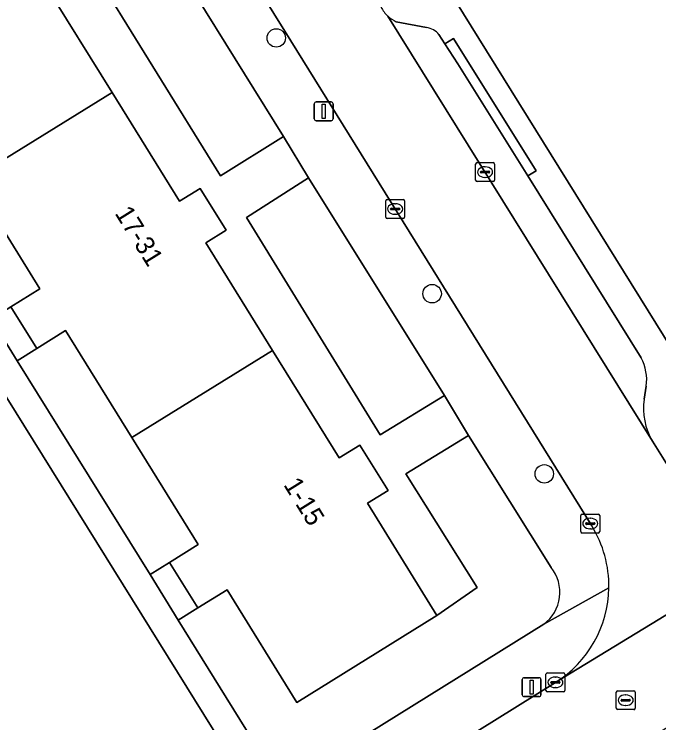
# Model space of a CAD drawing. Extents: x 160030 to 160839, y 385325 to 386450.
# Drawn here: x 160299.48 to 160333.64, y 386175.84 to 386213.39 of the extents above; entities that cross this region are included whole.
import ezdxf

# ---------------------------------------------------------------- set-up
doc = ezdxf.new("R2010")
doc.units = 0
for name, color, linetype in [('IMGEO_Boom', 7, 'Continuous'), ('IMGEO_Erf', 7, 'Continuous'), ('IMGEO_Groenvoorziening', 7, 'Continuous'), ('IMGEO_Haag', 7, 'Continuous'), ('IMGEO_Kolk', 7, 'Continuous'), ('IMGEO_Lichtmast', 7, 'Continuous'), ('IMGEO_Pand', 7, 'Continuous'), ('IMGEO_Pand_nummerreeks', 7, 'Continuous'), ('IMGEO_Parkeervlak_open', 7, 'Continuous'), ('IMGEO_Rijbaan_lokaal_open', 7, 'Continuous'), ('IMGEO_Rioolput', 7, 'Continuous'), ('IMGEO_Voetpad_op_trap', 7, 'Continuous'), ('IMGEO_Voetpad_open', 7, 'Continuous')]:
    doc.layers.add(name, color=color, linetype=linetype)

msp = doc.modelspace()

# ---------------------------------------------------------------- linework, layer by layer
at = {"layer": 'IMGEO_Boom'}
for centre in [(160313.371, 386212.128), (160321.633, 386198.577), (160327.575, 386189.032)]:
    msp.add_circle(centre, 0.489, dxfattribs=at)
at = {"layer": 'IMGEO_Erf'}
msp.add_lwpolyline([(160304.123, 386244.251), (160337.312, 386190.843)], dxfattribs=at)
at = {"layer": 'IMGEO_Groenvoorziening'}
for points in [[(160301.386, 386164.795), (160312.412, 386171.653), (160275.723, 386230.616), (160264.734, 386223.762)], [(160327.936, 386184.073), (160323.561, 386191.066), (160320.231, 386189.03), (160324.014, 386183.004), (160321.888, 386181.533), (160314.462, 386176.925), (160310.764, 386182.883), (160309.22, 386181.925), (160308.182, 386181.28), (160313.676, 386172.439), (160327.55, 386181.067)]]:
    msp.add_lwpolyline(points, dxfattribs=at)
for points in [[(160306.568, 386218.474), (160303.238, 386216.424), (160310.423, 386204.827), (160313.752, 386206.898)], [(160293.617, 386210.48), (160292.05, 386209.507), (160291.031, 386208.874), (160298.269, 386197.229), (160299.312, 386197.878), (160300.847, 386198.83), (160297.243, 386204.638)], [(160315.078, 386204.713), (160311.788, 386202.622), (160318.885, 386191.095), (160322.284, 386193.185)], [(160305.72, 386190.952), (160302.202, 386196.621), (160300.679, 386195.676), (160299.637, 386195.028), (160306.682, 386183.693), (160307.722, 386184.339), (160309.24, 386185.281)]]:
    msp.add_lwpolyline(points, close=True, dxfattribs=at)
msp.add_arc((160326.298, 386182.756), 2.102, 306.5541, 38.8113, dxfattribs=at)
at = {"layer": 'IMGEO_Haag'}
for points in [[(160306.568, 386218.474), (160303.238, 386216.424), (160310.423, 386204.827), (160313.752, 386206.898)], [(160315.078, 386204.713), (160311.788, 386202.622), (160318.885, 386191.095), (160322.284, 386193.185)]]:
    msp.add_lwpolyline(points, close=True, dxfattribs=at)
at = {"layer": 'IMGEO_Kolk'}
for p, q in [((160323.937, 386204.594), (160323.937, 386205.446)), ((160324.012, 386205.52), (160324.864, 386205.52)), ((160324.425, 386205.3), (160324.45, 386205.3)), ((160324.938, 386205.446), (160324.938, 386204.594)), ((160324.196, 386205.014), (160324.196, 386205.026)), ((160324.634, 386204.977), (160324.236, 386204.977)), ((160324.239, 386205.063), (160324.637, 386205.063)), ((160324.68, 386205.026), (160324.68, 386205.014)), ((160324.864, 386204.52), (160324.012, 386204.52)), ((160324.448, 386204.74), (160324.423, 386204.74)), ((160319.17, 386202.64), (160319.17, 386203.492)), ((160319.245, 386203.566), (160320.097, 386203.566)), ((160319.658, 386203.346), (160319.683, 386203.346)), ((160320.171, 386203.492), (160320.171, 386202.64)), ((160319.429, 386203.06), (160319.429, 386203.072)), ((160319.867, 386203.023), (160319.469, 386203.023)), ((160319.472, 386203.109), (160319.87, 386203.109)), ((160319.913, 386203.072), (160319.913, 386203.06)), ((160320.097, 386202.566), (160319.245, 386202.566)), ((160319.681, 386202.786), (160319.656, 386202.786)), ((160329.511, 386185.971), (160329.511, 386186.823)), ((160329.586, 386186.897), (160330.438, 386186.897)), ((160330.512, 386186.823), (160330.512, 386185.971)), ((160329.813, 386186.44), (160330.211, 386186.44)), ((160329.999, 386186.677), (160330.024, 386186.677)), ((160329.77, 386186.391), (160329.77, 386186.403)), ((160330.208, 386186.354), (160329.81, 386186.354)), ((160330.022, 386186.117), (160329.997, 386186.117)), ((160330.254, 386186.403), (160330.254, 386186.391)), ((160330.438, 386185.897), (160329.586, 386185.897)), ((160327.663, 386177.557), (160327.663, 386178.409)), ((160327.738, 386178.483), (160328.59, 386178.483)), ((160328.151, 386178.263), (160328.176, 386178.263)), ((160328.664, 386178.409), (160328.664, 386177.557)), ((160327.922, 386177.977), (160327.922, 386177.989)), ((160328.36, 386177.94), (160327.962, 386177.94)), ((160327.965, 386178.026), (160328.363, 386178.026)), ((160328.406, 386177.989), (160328.406, 386177.977)), ((160328.59, 386177.483), (160327.738, 386177.483)), ((160328.174, 386177.703), (160328.149, 386177.703))]:
    msp.add_line(p, q, dxfattribs=at)
for points in [[(160323.937, 386204.594), (160323.937, 386205.446)], [(160324.012, 386205.52), (160324.864, 386205.52)], [(160324.938, 386205.446), (160324.938, 386204.594)], [(160324.864, 386204.52), (160324.012, 386204.52)], [(160319.17, 386202.64), (160319.17, 386203.492)], [(160319.245, 386203.566), (160320.097, 386203.566)], [(160320.171, 386203.492), (160320.171, 386202.64)], [(160320.097, 386202.566), (160319.245, 386202.566)], [(160329.511, 386185.971), (160329.511, 386186.823)], [(160329.586, 386186.897), (160330.438, 386186.897)], [(160330.512, 386186.823), (160330.512, 386185.971)], [(160330.438, 386185.897), (160329.586, 386185.897)], [(160327.663, 386177.557), (160327.663, 386178.409)], [(160327.738, 386178.483), (160328.59, 386178.483)], [(160328.664, 386178.409), (160328.664, 386177.557)], [(160328.59, 386177.483), (160327.738, 386177.483)]]:
    msp.add_lwpolyline(points, dxfattribs=at)
for centre, radius, start, end in [((160324.014, 386205.444), 0.0765, 91.552, 178.448), ((160324.014, 386205.444), 0.0765, 91.552, 178.448), ((160324.862, 386205.444), 0.0765, 1.552, 88.448), ((160324.862, 386205.444), 0.0765, 1.552, 88.448), ((160324.236, 386205.023), 0.0403, 85.8775, 175.7526), ((160324.233, 386205.013), 0.0366, 178.938, 274.7102), ((160324.637, 386205.02), 0.043, 264.8664, 352.4533), ((160324.641, 386205.025), 0.0386, 1.7309, 96.639), ((160324.014, 386204.596), 0.0765, 181.552, 268.448), ((160324.014, 386204.596), 0.0765, 181.552, 268.448), ((160324.862, 386204.596), 0.0765, 271.552, 358.448), ((160324.862, 386204.596), 0.0765, 271.552, 358.448), ((160319.247, 386203.49), 0.0765, 91.552, 178.448), ((160319.247, 386203.49), 0.0765, 91.552, 178.448), ((160320.095, 386203.49), 0.0765, 1.552, 88.448), ((160320.095, 386203.49), 0.0765, 1.552, 88.448), ((160319.469, 386203.069), 0.0403, 85.8775, 175.7526), ((160319.466, 386203.059), 0.0366, 178.938, 274.7102), ((160319.87, 386203.066), 0.043, 264.8664, 352.4533), ((160319.874, 386203.071), 0.0386, 1.7309, 96.639), ((160319.247, 386202.642), 0.0765, 181.552, 268.448), ((160319.247, 386202.642), 0.0765, 181.552, 268.448), ((160320.095, 386202.642), 0.0765, 271.552, 358.448), ((160320.095, 386202.642), 0.0765, 271.552, 358.448), ((160329.588, 386186.821), 0.0765, 91.552, 178.448), ((160329.588, 386186.821), 0.0765, 91.552, 178.448), ((160330.436, 386186.821), 0.0765, 1.552, 88.448), ((160330.436, 386186.821), 0.0765, 1.552, 88.448), ((160329.81, 386186.4), 0.0403, 85.8775, 175.7526), ((160330.215, 386186.402), 0.0386, 1.7309, 96.639), ((160329.807, 386186.39), 0.0366, 178.938, 274.7102), ((160330.211, 386186.397), 0.043, 264.8664, 352.4533), ((160329.588, 386185.973), 0.0765, 181.552, 268.448), ((160329.588, 386185.973), 0.0765, 181.552, 268.448), ((160330.436, 386185.973), 0.0765, 271.552, 358.448), ((160330.436, 386185.973), 0.0765, 271.552, 358.448), ((160327.74, 386178.407), 0.0765, 91.552, 178.448), ((160327.74, 386178.407), 0.0765, 91.552, 178.448), ((160328.588, 386178.407), 0.0765, 1.552, 88.448), ((160328.588, 386178.407), 0.0765, 1.552, 88.448), ((160327.962, 386177.986), 0.0403, 85.8775, 175.7526), ((160327.959, 386177.976), 0.0366, 178.938, 274.7102), ((160328.363, 386177.983), 0.043, 264.8664, 352.4533), ((160328.367, 386177.988), 0.0386, 1.7309, 96.639), ((160327.74, 386177.559), 0.0765, 181.552, 268.448), ((160327.74, 386177.559), 0.0765, 181.552, 268.448), ((160328.588, 386177.559), 0.0765, 271.552, 358.448), ((160328.588, 386177.559), 0.0765, 271.552, 358.448)]:
    msp.add_arc(centre, radius, start, end, dxfattribs=at)
for centre, major_axis, ratio, start_param, end_param in [((160324.424, 386205.02), (-0.387, 0.002), 0.722429, 4.712389, 7.853982), ((160324.449, 386205.02), (-0.39, 0.002), 0.717154, 1.570796, 4.712389), ((160319.657, 386203.066), (-0.387, 0.002), 0.722429, 4.712389, 7.853982), ((160319.682, 386203.066), (-0.39, 0.002), 0.717154, 1.570796, 4.712389), ((160329.998, 386186.397), (-0.387, 0.002), 0.722429, 4.712389, 7.853982), ((160330.023, 386186.397), (-0.39, 0.002), 0.717154, 1.570796, 4.712389), ((160328.15, 386177.983), (-0.387, 0.002), 0.722429, 4.712389, 7.853982), ((160328.175, 386177.983), (-0.39, 0.002), 0.717154, 1.570796, 4.712389)]:
    msp.add_ellipse(centre, major_axis=major_axis, ratio=ratio, start_param=start_param, end_param=end_param, dxfattribs=at)
at = {"layer": 'IMGEO_Lichtmast'}
for p, q in [((160315.389, 386207.842), (160315.389, 386208.642)), ((160315.389, 386208.642), (160315.389, 386207.842)), ((160315.489, 386208.742), (160316.279, 386208.742)), ((160316.279, 386208.742), (160315.489, 386208.742)), ((160316.379, 386208.642), (160316.379, 386207.842)), ((160316.379, 386207.842), (160316.379, 386208.642)), ((160316.279, 386207.742), (160315.489, 386207.742)), ((160315.489, 386207.742), (160316.279, 386207.742)), ((160326.509, 386178.227), (160327.299, 386178.227)), ((160327.299, 386178.227), (160326.509, 386178.227)), ((160326.409, 386177.327), (160326.409, 386178.127)), ((160326.409, 386178.127), (160326.409, 386177.327)), ((160327.399, 386178.127), (160327.399, 386177.327)), ((160327.399, 386177.327), (160327.399, 386178.127)), ((160327.299, 386177.227), (160326.509, 386177.227)), ((160326.509, 386177.227), (160327.299, 386177.227))]:
    msp.add_line(p, q, dxfattribs=at)
for points in [[(160315.809, 386208.617), (160315.959, 386208.617), (160315.959, 386207.867), (160315.809, 386207.867), (160315.809, 386208.617)], [(160326.829, 386178.102), (160326.979, 386178.102), (160326.979, 386177.352), (160326.829, 386177.352), (160326.829, 386178.102)]]:
    msp.add_lwpolyline(points, dxfattribs=at)
for centre, start, end in [((160315.489, 386208.642), 90, 180), ((160315.489, 386208.642), 90, 180), ((160316.279, 386208.642), 0, 90), ((160316.279, 386208.642), 360, 90), ((160315.489, 386207.842), 180, 270), ((160315.489, 386207.842), 180, 270), ((160316.279, 386207.842), 270, 0), ((160316.279, 386207.842), 270, 0), ((160326.509, 386178.127), 90, 180), ((160326.509, 386178.127), 90, 180), ((160327.299, 386178.127), 0, 90), ((160327.299, 386178.127), 360, 90), ((160326.509, 386177.327), 180, 270), ((160326.509, 386177.327), 180, 270), ((160327.299, 386177.327), 270, 0), ((160327.299, 386177.327), 270, 0)]:
    msp.add_arc(centre, 0.1, start, end, dxfattribs=at)
at = {"layer": 'IMGEO_Pand'}
for points in [[(160292.134, 386212.815), (160290.591, 386211.858), (160292.05, 386209.507), (160293.617, 386210.48), (160297.243, 386204.638), (160304.668, 386209.246), (160301.085, 386215.019), (160302.179, 386215.698), (160300.735, 386218.025), (160299.642, 386217.346), (160296.083, 386223.081), (160288.633, 386218.457)], [(160309.632, 386201.274), (160310.716, 386201.947), (160309.347, 386204.154), (160308.251, 386203.473), (160304.668, 386209.246), (160297.243, 386204.638), (160300.847, 386198.83), (160299.312, 386197.878), (160300.679, 386195.676), (160302.202, 386196.621), (160305.72, 386190.952), (160313.169, 386195.575)], [(160318.202, 386187.472), (160319.298, 386188.152), (160317.805, 386190.558), (160316.705, 386189.876), (160313.169, 386195.575), (160305.72, 386190.952), (160309.24, 386185.281), (160307.722, 386184.339), (160309.22, 386181.925), (160310.764, 386182.883), (160314.462, 386176.925), (160321.888, 386181.533)]]:
    msp.add_lwpolyline(points, close=True, dxfattribs=at)
at = {"layer": 'IMGEO_Parkeervlak_open'}
for points in [[(160319.29, 386213.287), (160333.315, 386190.762)], [(160321.331, 386212.684), (160319.733, 386212.99)], [(160322.309, 386211.819), (160321.995, 386212.306)], [(160322.991, 386210.759), (160322.309, 386211.819)], [(160326.706, 386204.817), (160322.991, 386210.759)], [(160332.704, 386195.176), (160326.706, 386204.817)], [(160332.867, 386192.983), (160332.978, 386193.672)]]:
    msp.add_lwpolyline(points, dxfattribs=at)
for centre, radius, start, end in [((160320.519, 386214.641), 1.828, 227.7743, 244.5476), ((160321.157, 386211.605), 1.093, 39.8825, 80.8138), ((160330.565, 386194.009), 2.437, 352.0445, 28.6054), ((160336.139, 386192.487), 3.309, 171.3859, 211.4224)]:
    msp.add_arc(centre, radius, start, end, dxfattribs=at)
at = {"layer": 'IMGEO_Rijbaan_lokaal_open'}
for points in [[(160296.637, 386240.069), (160313.825, 386212.492), (160330.091, 386186.273)], [(160334.54, 386188.784), (160333.315, 386190.762), (160319.29, 386213.287)], [(160296.772, 386152.353), (160320.685, 386167.257), (160326.329, 386170.774), (160326.552, 386170.947), (160340.383, 386179.474), (160340.53, 386179.543), (160347.326, 386183.769), (160344.612, 386188.134), (160343.862, 386187.679), (160342.893, 386187.018), (160342.516, 386186.712), (160328.191, 386177.996), (160328.161, 386177.98), (160316.882, 386170.942), (160304.012, 386162.957), (160303.952, 386162.913), (160289.843, 386154.224)], [(160328.161, 386177.98), (160328.191, 386177.996), (160342.516, 386186.712), (160342.893, 386187.018)]]:
    msp.add_lwpolyline(points, dxfattribs=at)
for centre, radius, start, end in [((160320.534, 386214.645), 1.841, 208.7918, 227.5119), ((160324.978, 386183.096), 6.019, 358.9949, 31.8606), ((160324.97, 386183.094), 6.028, 301.9631, 359.0113)]:
    msp.add_arc(centre, radius, start, end, dxfattribs=at)
at = {"layer": 'IMGEO_Rioolput'}
for p, q in [((160331.388, 386176.611), (160331.388, 386177.463)), ((160331.463, 386177.537), (160332.315, 386177.537)), ((160332.389, 386177.463), (160332.389, 386176.611)), ((160331.647, 386177.031), (160331.647, 386177.043)), ((160331.69, 386177.08), (160332.088, 386177.08)), ((160331.876, 386177.317), (160331.901, 386177.317)), ((160332.131, 386177.043), (160332.131, 386177.031)), ((160332.085, 386176.994), (160331.687, 386176.994)), ((160331.899, 386176.757), (160331.874, 386176.757)), ((160332.315, 386176.537), (160331.463, 386176.537))]:
    msp.add_line(p, q, dxfattribs=at)
for points in [[(160331.388, 386176.611), (160331.388, 386177.463)], [(160331.463, 386177.537), (160332.315, 386177.537)], [(160332.389, 386177.463), (160332.389, 386176.611)], [(160332.315, 386176.537), (160331.463, 386176.537)]]:
    msp.add_lwpolyline(points, dxfattribs=at)
for centre, radius, start, end in [((160331.465, 386177.461), 0.0765, 91.552, 178.448), ((160331.465, 386177.461), 0.0765, 91.552, 178.448), ((160332.313, 386177.461), 0.0765, 1.552, 88.448), ((160332.313, 386177.461), 0.0765, 1.552, 88.448), ((160331.687, 386177.04), 0.0403, 85.8775, 175.7526), ((160331.684, 386177.03), 0.0366, 178.938, 274.7102), ((160332.088, 386177.037), 0.043, 264.8664, 352.4533), ((160332.092, 386177.042), 0.0386, 1.7309, 96.639), ((160331.465, 386176.613), 0.0765, 181.552, 268.448), ((160331.465, 386176.613), 0.0765, 181.552, 268.448), ((160332.313, 386176.613), 0.0765, 271.552, 358.448), ((160332.313, 386176.613), 0.0765, 271.552, 358.448)]:
    msp.add_arc(centre, radius, start, end, dxfattribs=at)
for centre, major_axis, ratio, start_param, end_param in [((160331.875, 386177.037), (-0.387, 0.002), 0.722429, 4.712389, 7.853982), ((160331.9, 386177.037), (-0.39, 0.002), 0.717154, 1.570796, 4.712389)]:
    msp.add_ellipse(centre, major_axis=major_axis, ratio=ratio, start_param=start_param, end_param=end_param, dxfattribs=at)
at = {"layer": 'IMGEO_Voetpad_op_trap'}
for points in [[(160299.312, 386197.878), (160298.269, 386197.229), (160299.637, 386195.028), (160300.679, 386195.676)], [(160307.722, 386184.339), (160306.682, 386183.693), (160308.182, 386181.28), (160309.22, 386181.925)]]:
    msp.add_lwpolyline(points, close=True, dxfattribs=at)
at = {"layer": 'IMGEO_Voetpad_open'}
for points in [[(160337.312, 386190.843), (160304.123, 386244.251)], [(160330.091, 386186.273), (160313.825, 386212.492), (160296.637, 386240.069)], [(160293.789, 386238.957), (160296.634, 386234.322), (160297.972, 386232.133), (160305.162, 386220.629), (160306.568, 386218.474), (160313.752, 386206.898), (160315.078, 386204.713), (160322.284, 386193.185), (160323.561, 386191.066), (160327.936, 386184.073)], [(160301.085, 386215.019), (160304.668, 386209.246), (160308.251, 386203.473), (160309.347, 386204.154), (160310.716, 386201.947), (160309.632, 386201.274), (160313.169, 386195.575), (160316.705, 386189.876), (160317.805, 386190.558), (160319.298, 386188.152), (160318.202, 386187.472), (160321.888, 386181.533), (160324.014, 386183.004), (160320.231, 386189.03), (160323.561, 386191.066), (160322.284, 386193.185), (160318.885, 386191.095), (160311.788, 386202.622), (160315.078, 386204.713), (160313.752, 386206.898), (160310.423, 386204.827), (160303.238, 386216.424)], [(160319.733, 386212.99), (160321.331, 386212.684)], [(160321.995, 386212.306), (160322.309, 386211.819), (160322.771, 386212.107), (160327.137, 386205.085), (160326.706, 386204.817), (160332.704, 386195.176)], [(160332.978, 386193.672), (160332.867, 386192.983)], [(160333.315, 386190.762), (160334.54, 386188.784)], [(160330.997, 386182.99), (160327.55, 386181.067), (160313.676, 386172.439), (160312.412, 386171.653), (160301.386, 386164.795), (160299.545, 386162.244)], [(160327.55, 386181.067), (160330.997, 386182.99)], [(160304.012, 386162.957), (160316.882, 386170.942), (160328.161, 386177.98)]]:
    msp.add_lwpolyline(points, dxfattribs=at)
for points in [[(160291.031, 386208.874), (160289.571, 386211.224), (160282.479, 386222.634), (160281.048, 386224.938), (160277.017, 386231.423), (160275.723, 386230.616), (160312.412, 386171.653), (160313.676, 386172.439), (160308.182, 386181.28), (160306.682, 386183.693), (160299.637, 386195.028), (160298.269, 386197.229)], [(160326.706, 386204.817), (160327.137, 386205.085), (160322.771, 386212.107), (160322.309, 386211.819), (160322.991, 386210.759)]]:
    msp.add_lwpolyline(points, close=True, dxfattribs=at)
for centre, radius, start, end in [((160320.534, 386214.645), 1.841, 208.7918, 227.5119), ((160320.519, 386214.641), 1.828, 227.7743, 244.5476), ((160321.157, 386211.605), 1.093, 39.8825, 80.8138), ((160330.565, 386194.009), 2.437, 352.0445, 28.6054), ((160336.139, 386192.487), 3.309, 171.3859, 211.4224), ((160324.978, 386183.096), 6.019, 358.9949, 31.8606), ((160326.298, 386182.756), 2.102, 306.5541, 38.8113), ((160324.97, 386183.094), 6.028, 301.9631, 359.0113)]:
    msp.add_arc(centre, radius, start, end, dxfattribs=at)

# ---------------------------------------------------------------- texts
at = {"layer": 'IMGEO_Pand_nummerreeks'}
for s, rotation, p in [('17-31', 301.873, (160304.789, 386202.839)), ('1-15', 301.8386, (160313.729, 386188.455))]:
    msp.add_text(s, height=1, rotation=rotation, dxfattribs=at).set_placement(p)

doc.saveas('drawing.dxf')
